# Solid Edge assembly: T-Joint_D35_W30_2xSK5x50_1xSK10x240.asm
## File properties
Author: fknapp
Template: iso metric assembly.asm
Last saved by: fknapp
Revision: 8
Application: Solid Edge
Username: fknapp
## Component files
T-Joint_D35_W30.par
SK Schraube 5x50_ohne_Gewinde.par
SK Schraube 10x240_ohne_Gewinde_22042020.par
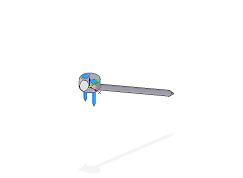
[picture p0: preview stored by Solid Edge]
